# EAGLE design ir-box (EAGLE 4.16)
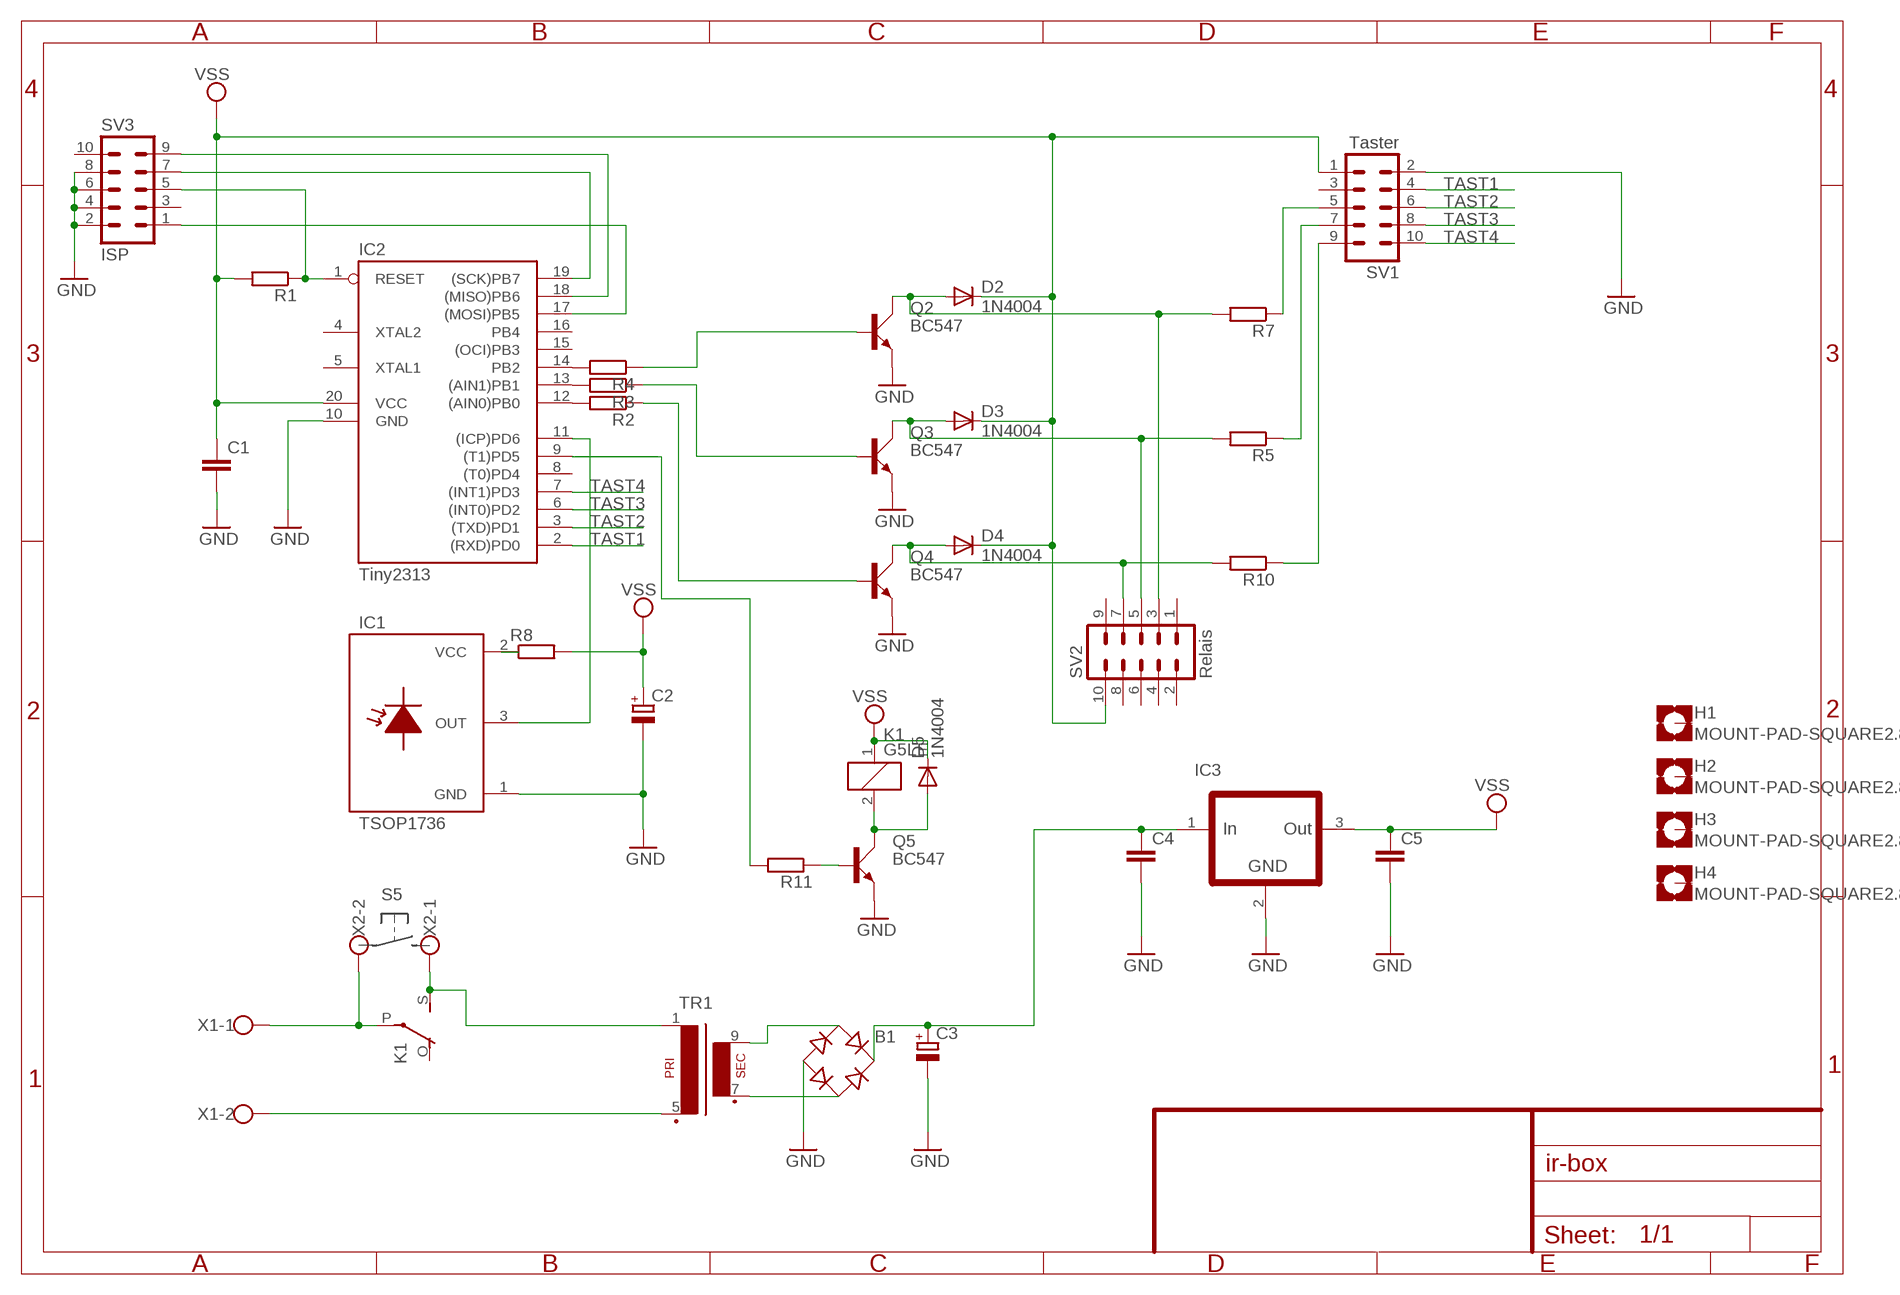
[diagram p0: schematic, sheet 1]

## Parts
B1  B-DIL  [B-DIL]
C1  C-EU050-025X075  [C050-025X075]
C2  CPOL-EUE3.5-8  [E3,5-8]
C3  CPOL-EUE5-13  [E5-13]
C4  C-EU050-025X075  [C050-025X075]
C5  C-EU050-025X075  [C050-025X075]
D2  1N4004  [DO41-10]
D3  1N4004  [DO41-10]
D4  1N4004  [DO41-10]
D5  1N4004  [DO41-10]
H1  MOUNT-PAD-SQUARE2.8  [2,8-PAD-SQUARE]
H2  MOUNT-PAD-SQUARE2.8  [2,8-PAD-SQUARE]
H3  MOUNT-PAD-SQUARE2.8  [2,8-PAD-SQUARE]
H4  MOUNT-PAD-SQUARE2.8  [2,8-PAD-SQUARE]
IC1  TSOP1736  [TSOP]
IC2  Tiny2313  AT90S2313P  [DIL20]
IC3  78XX  [TO220AV]
K1  G5LE  [G5LE]
Q2  BC547  [SOT54A]
Q3  BC547  [SOT54A]
Q4  BC547  [SOT54A]
Q5  BC547  [SOT54A]
R1  R-EU_0204/7  [0204/7]
R2  R-EU_0204/7  [0204/7]
R3  R-EU_0204/7  [0204/7]
R4  R-EU_0204/7  [0204/7]
R5  R-EU_0204/7  [0204/7]
R7  R-EU_0204/7  [0204/7]
R8  R-EU_0204/7  [0204/7]
R10  R-EU_0204/7  [0204/7]
R11  R-EU_0204/7  [0204/7]
SV1  Taster  ML10  [ML10]
SV2  Relais  ML10  [ML10]
SV3  ISP  ML10  [ML10]
TR1  EI42-1  [EI42-1]
X1  W237-2N  [W237-2N]
X2  W237-2N  [W237-2N]

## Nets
GND: B1.- C1.2 C2.- C3.- C4.2 C5.2 IC1.1(GND) IC2.10(GND) IC3.2(GND) Q2.E Q3.E Q4.E Q5.E SV1.2 SV3.2 SV3.4 SV3.6 SV3.8
N$1: IC2.12((AIN0)PB0) R2.2
N$2: IC2.1(RESET) R1.1 SV3.5
N$3: IC2.13((AIN1)PB1) R3.2
N$4: IC2.14(PB2) R4.2
N$7: Q2.B R4.1
N$8: Q3.B R3.1
N$9: Q4.B R2.1
N$11: D2.A Q2.C R7.2 SV2.3
N$12: D3.A Q3.C R5.2 SV2.5
N$13: D4.A Q4.C R10.2 SV2.7
N$14: IC1.3(OUT) IC2.11((ICP)PD6)
N$15: IC1.2(VCC) R8.1
N$16: K1.P(2:P) X1.1 X2.2
N$17: K1.S(2:S) TR1.1 X2.1
N$18: TR1.5 X1.2
N$19: B1.AC2 TR1.7
N$20: B1.AC1 TR1.9
N$21: Q5.B R11.1
N$22: B1.+ C3.+ C4.1 IC3.1(IN)
N$23: D5.A K1.2 Q5.C
N$25: IC2.9((T1)PD5) R11.2
N$27: R7.1 SV1.5
N$28: R5.1 SV1.7
N$29: R10.1 SV1.9
N$30: IC2.17((MOSI)PB5) SV3.1
N$31: IC2.19((SCK)PB7) SV3.7
N$32: IC2.18((MISO)PB6) SV3.9
TAST1: IC2.2((RXD)PD0) SV1.4
TAST2: IC2.3((TXD)PD1) SV1.6
TAST3: IC2.6((INT0)PD2) SV1.8
TAST4: IC2.7((INT1)PD3) SV1.10
VSS: C1.1 C2.+ C5.1 D2.C D3.C D4.C D5.C IC2.20(VCC) IC3.3(OUT) K1.1 R1.2 R8.2 SV1.1 SV2.10
Unconnected: H1.B2,8(MOUNT) H2.B2,8(MOUNT) H3.B2,8(MOUNT) H4.B2,8(MOUNT) IC2.4(XTAL2) IC2.5(XTAL1) IC2.8((T0)PD4) IC2.15((OCI)PB3) IC2.16(PB4) K1.O(2:O) SV1.3 SV2.1 SV2.2 SV2.4 SV2.6 SV2.8 SV2.9 SV3.3 SV3.10

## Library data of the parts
B1 = rectifier:B-DIL: RECTIFIER
C1 C4 C5 = rcl:C-EU: CAPACITOR, European symbol
C2 C3 = rcl:CPOL-EU: POLARIZED CAPACITOR, European symbol
D2-D5 = diode-1:1N4004: DIODE
H1-H4 = holes:MOUNT-PAD-SQUARE: MOUNTING PAD, square
IC1 = andereBauteile:TSOP: TSOP17.. Photo Modules for PCM Remote Control Systems
IC2 = avr:AT90S2313: MICROCONTROLLER 2 Kbytes FLASH 128 bytes SRAM 128 bytes EEPROM UART
IC3 = 0_jmw:78XX
K1 = relay:G5LE: RELAY 1 x switch, 10 A/120 V AC, 8 A/30 V DC, Omron
Q2-Q5 = transistor-small-signal:BC547: NPN TRANSISTOR
R1-R5 R7 R8 R10 R11 = rcl:R-EU_: RESISTOR, European symbol
SV1-SV3 = con-ml:ML10: HARTING
TR1 = trafo:EI42-1: TRANSFORMER 1 primary winding, 1 secondary winding ERA
X1 X2 = con-wago-508:W237-2N: WAGO SREW CLAMP

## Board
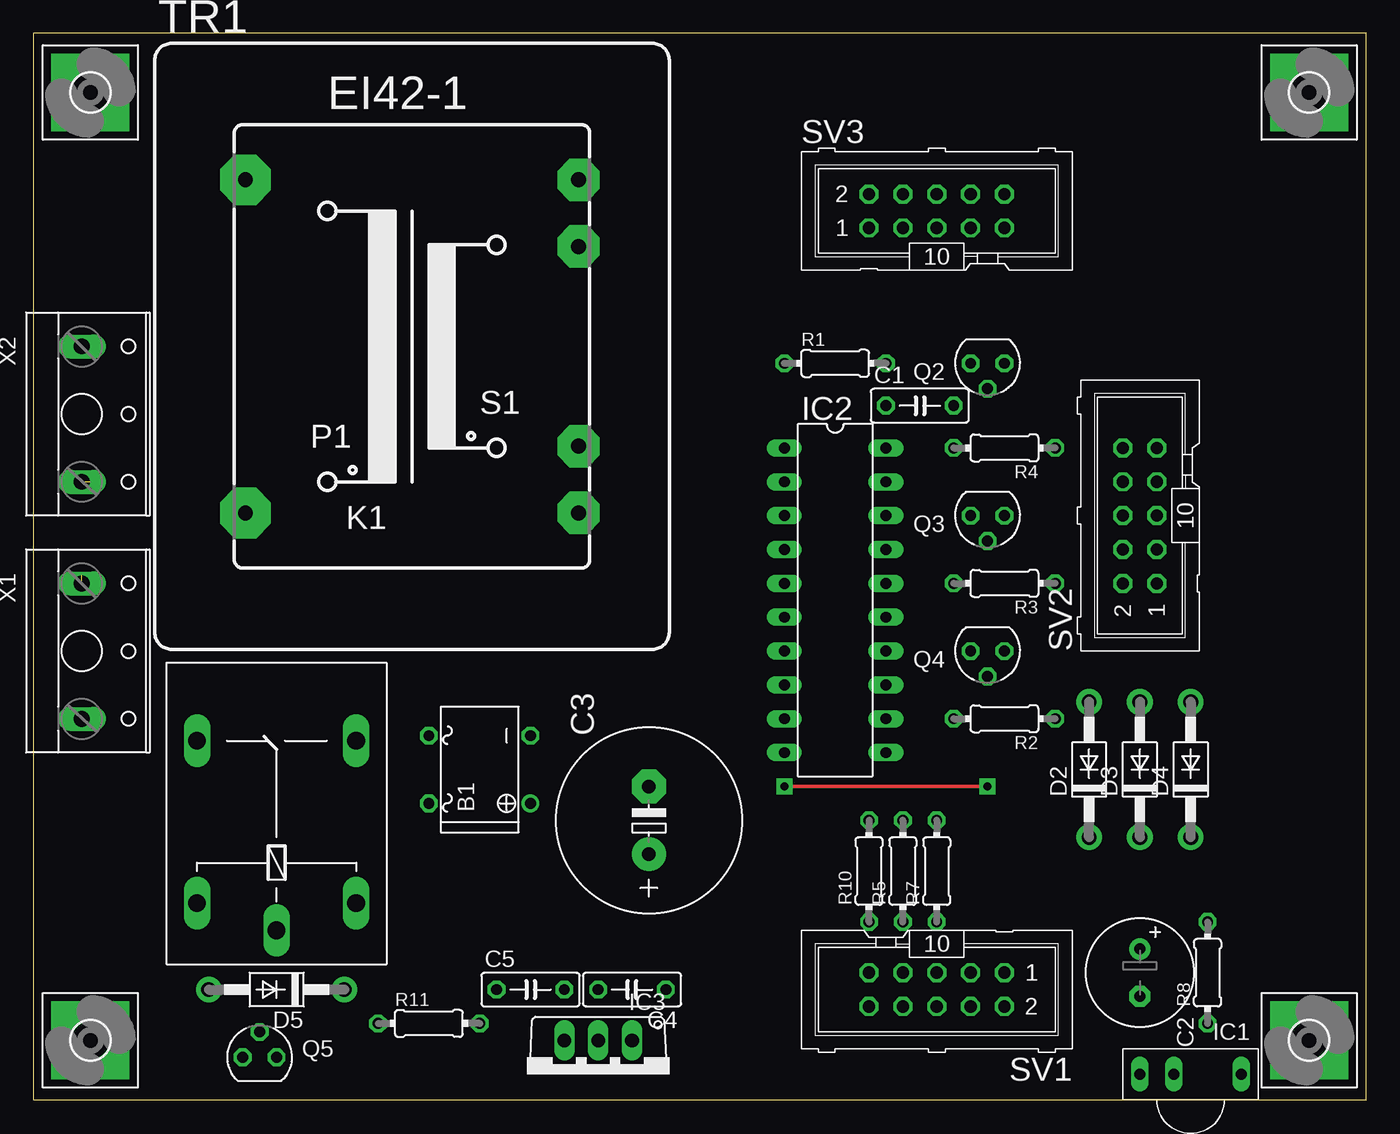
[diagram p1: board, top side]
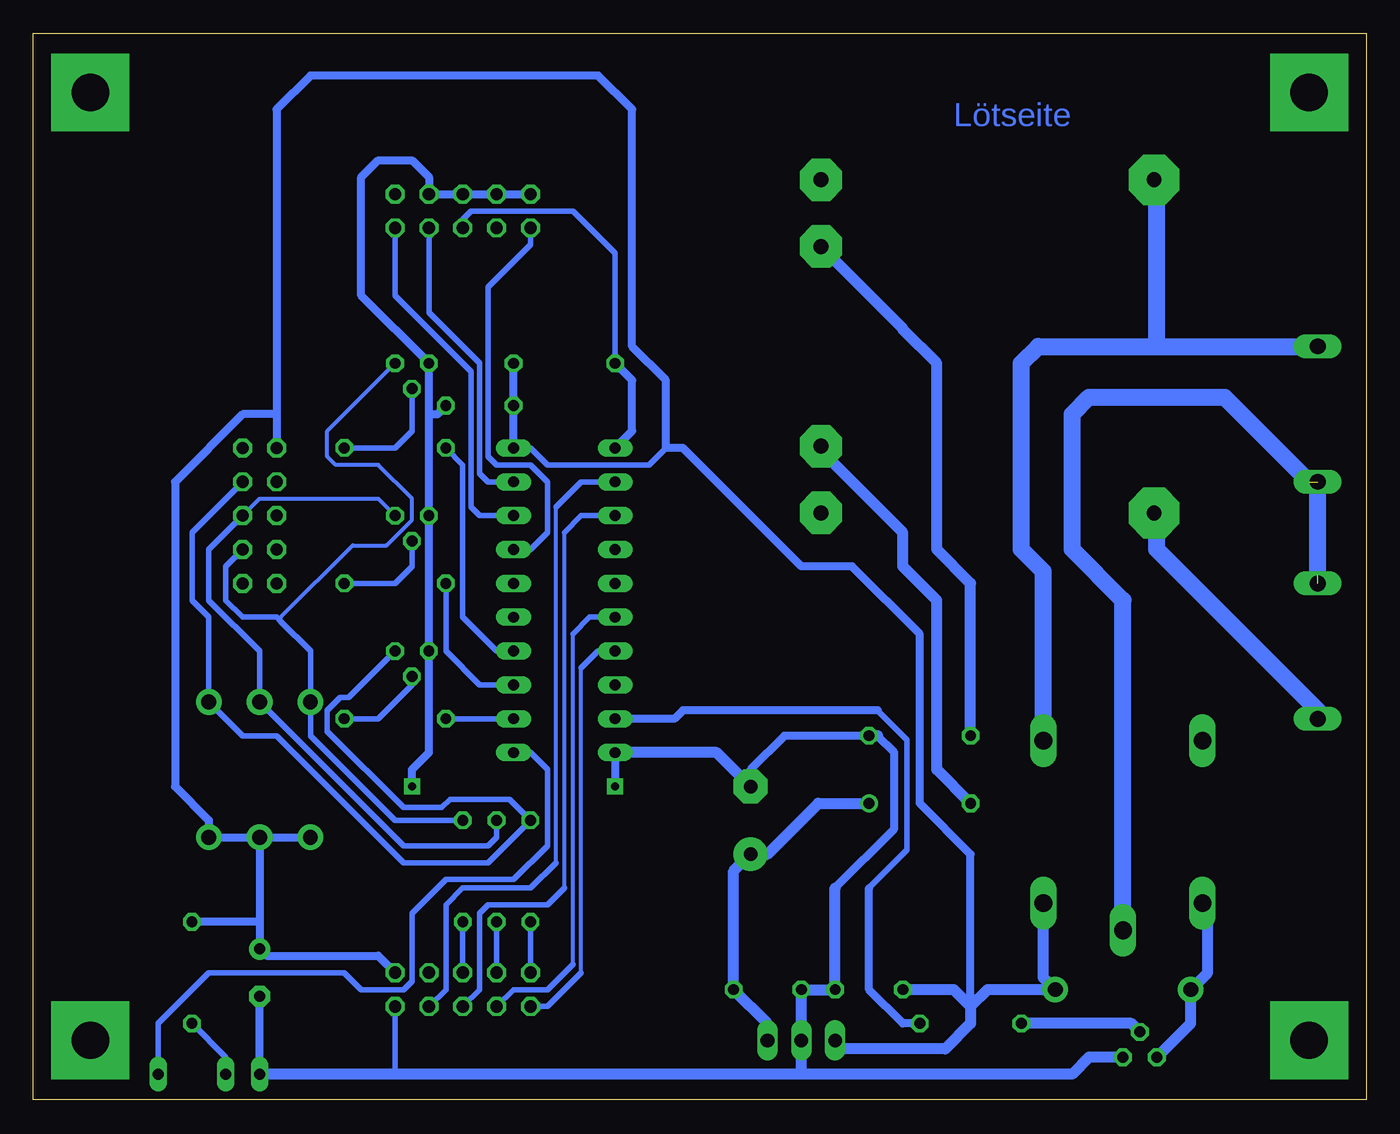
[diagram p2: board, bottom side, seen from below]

Size 100 x 80 mm. Coordinates in mm from the lower left corner, seen from the top.
Outline: 0,0 100,0 100,80 0,80 0,0
Copper layers (1*16): Top 0.035mm / dielectric 1.5mm / Bottom 0.035mm
Design rules "default": minimum track width 10mil, minimum drill 0.4mm, track to track 10mil, track to pad 10mil, pad to pad 10mil, via to via 10mil, smd to smd 10mil, copper to edge 40mil, drill to drill 8mil, minimum pad ring 10mil, minimum via ring 0.3mm, stop-mask expansion 4mil, vias tented up to drill 0mil, thermal gap 10mil

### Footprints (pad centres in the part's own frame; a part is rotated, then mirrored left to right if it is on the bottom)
B-DIL = drill 0.813 round: + -2.54,-3.81 | drill 0.813 octagon: - 2.54,-3.81; AC1 2.54,3.81; AC2 -2.54,3.81
C050-025X075 = drill 0.813 octagon: 1 -2.54,0; 2 2.54,0
E3,5-8 = drill 0.813 pad 1.6 round: + -1.778,0 | drill 0.813 pad 1.6 octagon: - 1.778,0
E5-13 = drill 1.016 pad 2.54 round: + -2.54,0 | drill 1.016 pad 2.54 octagon: - 2.54,0
DO41-10 = drill 1.118 pad 1.93 round: A 5.08,0; C -5.08,0
2,8-PAD-SQUARE = drill 2.8 pad 5.842 square: B2,8 0,0
TSOP = drill 0.813 long: 1 3.81,0; 2 1.27,0; 3 -3.81,0
DIL20 = drill 0.813 long: 1 -11.43,-3.81; 2 -8.89,-3.81; 3 -6.35,-3.81; 4 -3.81,-3.81; 5 -1.27,-3.81; 6 1.27,-3.81; 7 3.81,-3.81; 8 6.35,-3.81; 9 8.89,-3.81; 10 11.43,-3.81; 11 11.43,3.81; 12 8.89,3.81; 13 6.35,3.81; 14 3.81,3.81; 15 1.27,3.81; 16 -1.27,3.81; 17 -3.81,3.81; 18 -6.35,3.81; 19 -8.89,3.81; 20 -11.43,3.81
TO220AV = drill 1.016 long: 1 -2.54,-2.54; 2 0,-2.54; 3 2.54,-2.54
G5LE = drill 1.321 long: 1 -7.493,-5.969; 2 -7.493,5.969; O 4.699,5.969; P -9.525,0; S 4.699,-5.969
SOT54A = drill 0.813 octagon: B 0,1.905; C -1.27,0; E 1.27,0
0204/7 = drill 0.813 octagon: 1 -3.81,0; 2 3.81,0
ML10 = drill 0.914 octagon: 1 -5.08,-1.27; 2 -5.08,1.27; 3 -2.54,-1.27; 4 -2.54,1.27; 5 0,-1.27; 6 0,1.27; 7 2.54,-1.27; 8 2.54,1.27; 9 5.08,-1.27; 10 5.08,1.27
EI42-1 = drill 1.118 pad 3.81 octagon: 1 -12.497,12.497; 5 -12.497,-12.497 | drill 1.118 pad 3.175 octagon: 6 12.497,-12.497; 7 12.497,-7.493; 9 12.497,7.493; 10 12.497,12.497
W237-2N = drill 1.194 long: 1 -5.08,-0.635; 2 5.08,-0.635

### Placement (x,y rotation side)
B1  33.49,24.76 90 top
C1  66.51,52.07 0 top
C2  83.02,9.52 270 top
C3  46.19,20.95 90 top
C4  44.92,8.25 180 top
C5  37.3,8.25 0 top
D2  79.21,24.76 90 top
D3  83.02,24.76 90 top
D4  86.83,24.76 90 top
D5  18.25,8.25 180 top
H1  4.28,4.44 0 top
H2  4.28,75.56 0 top
H3  95.72,75.56 0 top
H4  95.72,4.44 0 top
IC1  86.83,1.9 180 top
IC2  60.16,37.46 270 top
IC3  42.38,1.9 180 top
K1  18.25,22.22 90 top
Q2  71.59,55.24 180 top
Q3  71.59,43.81 180 top
Q4  71.59,33.65 180 top
Q5  16.98,3.17 0 top
R1  60.16,55.24 0 top
R2  72.86,28.57 180 top
R3  72.86,38.73 180 top
R4  72.86,48.89 180 top
R5  65.24,17.14 90 top
R7  67.78,17.14 90 top
R8  88.1,9.52 90 top
R10  62.7,17.14 90 top
R11  29.68,5.71 0 top
SV1  67.78,8.25 180 top
SV2  83.02,43.81 90 top
SV3  67.78,66.67 0 top
TR1  28.41,56.51 0 top
X1  4.28,33.65 270 top
X2  4.28,51.43 270 top

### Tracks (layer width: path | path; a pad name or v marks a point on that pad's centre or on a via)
GND  (via drill 0.6)
  Top 0.254: v56.35,23.49 v71.59,23.49
  Bottom 0.406: 72.86,1.9 SV1.2
  Bottom 0.61: B1.- 43.65,27.3 46.19,24.76 C3.- | 39.84,15.87 35.39,20.31 35.39,26.03 36.66,27.3 | IC1.1 C2.- | SV3.2 SV3.4 SV3.6 SV3.8 70.32,69.21 71.59,70.48 74.13,70.48 75.4,69.21 75.4,60.32 Q2.E 70.32,51.43 | 70.32,51.43 Q3.E Q4.E 70.32,26.03 71.59,24.76 v71.59,23.49 | C1.2 69.69,51.43 70.32,51.43 | IC2.10 v56.35,23.49
  Bottom 0.813: Q5.E 20.79,3.17 22.06,1.9 42.38,1.9 | 42.38,1.9 IC3.2 C4.2 | 42.38,1.9 72.86,1.9 IC1.1 | C4.2 C5.2 | IC2.10 48.73,26.03 C3.- | C4.2 C5.2 | C5.2 39.84,15.87 | 36.66,27.3 B1.-
N$1
  Bottom 0.406: IC2.12 R2.2
N$2
  Bottom 0.406: SV3.5 67.78,66.03 67.14,66.67 59.52,66.67 56.35,63.5 R1.1
  Bottom 0.61: R1.1 55.08,53.97 55.08,50.16 IC2.1
N$3
  Bottom 0.406: R3.2 69.05,33.65 66.51,31.11 IC2.13
N$4
  Bottom 0.406: R4.2 67.78,47.62 67.78,36.19 65.24,33.65 IC2.14
N$7
  Bottom 0.406: Q2.B 71.59,50.16 72.86,48.89 R4.1
N$8
  Bottom 0.406: Q3.B 71.59,40 72.86,38.73 R3.1
N$9
  Bottom 0.406: R2.1 74.13,28.57 71.59,31.11 Q4.B
N$11
  Bottom 0.305: Q2.C 77.94,50.16 77.94,48.26 77.3,47.62 74.13,47.62 71.59,45.08 71.59,43.49 73.5,41.59 76.03,41.59 81.43,36.19 81.43,35.87
  Bottom 0.406: SV2.3 85.56,40 85.56,37.46 84.29,36.19 81.75,36.19 81.43,35.87 79.21,33.65 D2.A 79.21,27.3 72.86,20.95 R7.2
N$12
  Bottom 0.305: SV2.5 83.02,45.08 74.13,45.08 Q3.C
  Bottom 0.406: SV2.5 86.83,41.27 86.83,37.46 83.02,33.65 D3.A 72.22,19.04 65.88,19.04 65.24,19.68 R5.2
N$13
  Bottom 0.406: SV2.7 88.1,42.54 88.1,37.46 86.83,36.19 D4.A 84.29,27.3 81.75,27.3 72.22,17.77 65.88,17.77 R10.2 64.29,22.54 68.73,22.54 69.37,21.9 72.22,21.9 77.94,27.62 77.94,29.2 76.99,30.16 76.35,30.16 Q4.C
N$14
  Bottom 0.406: IC2.11 62.7,26.03 61.43,24.76 61.43,19.04 63.97,16.5 69.05,16.5 71.59,13.97 71.59,8.89 72.22,8.25 75.4,8.25 76.67,9.52 77.3,9.52 86.83,9.52 90.64,5.71 IC1.3
N$15
  Bottom 0.406: IC1.2 85.56,3.17 R8.1
N$16  (2 unrouted)
  Bottom 1.27: X2.2 3.64,39.37 4.28,38.73 | K1.P 18.25,37.46 22.06,41.27 22.06,51.43 20.79,52.7 10.63,52.7 4.28,46.35
N$17
  Bottom 1.27: 15.71,69.01 15.71,69.21 | 15.71,69.01 TR1.1 | 15.71,56.51 X2.1 | 15.71,56.51 15.71,69.01 | K1.S 24.22,39.62 25.87,41.27 25.87,55.24 24.6,56.51 15.71,56.51
N$18
  Bottom 1.27: X1.2 3.64,29.2 15.71,41.27 15.71,43.81 TR1.5
N$19
  Bottom 0.813: TR1.7 41.03,48.89 41.11,48.89 34.76,42.54 34.76,40 32.22,37.46 32.22,24.76 B1.AC2
N$20
  Bottom 0.813: TR1.9 34.76,57.86 34.76,57.78 32.22,55.24 32.22,41.27 29.68,38.73 B1.AC1
N$21
  Bottom 0.813: Q5.B 17.61,5.71 R11.1
N$22
  Bottom 0.813: B1.+ 41.11,22.22 44.92,18.41 C3.+ 47.46,17.14 C4.1 44.92,5.71 IC3.1
N$23
  Bottom 0.813: Q5.C 13.17,5.71 D5.A 11.9,9.52 11.9,14.6 12.03,14.73 K1.2
N$25
  Bottom 0.406: 37.3,15.87 34.44,18.73 34.44,26.98 36.66,29.2
  Bottom 0.61: IC2.9 52.54,28.57 51.91,28.57 51.27,29.2 36.66,29.2 | R11.2 34.76,5.71 37.3,8.25 37.3,15.87
N$27
  Bottom 0.406: SV1.5 R7.1
N$28
  Bottom 0.406: SV1.7 R5.1
N$29
  Bottom 0.406: SV1.9 R10.1
N$30
  Bottom 0.406: SV3.1 62.7,64.13 65.88,60.96 65.88,48.26 65.24,47.62 62.7,47.62 61.43,46.35 61.43,42.54 62.7,41.27 IC2.17
N$31
  Bottom 0.406: IC2.19 65.88,46.35 66.51,46.98 66.51,55.24 70.32,59.05 SV3.7
N$32
  Bottom 0.406: IC2.18 66.51,43.81 67.14,44.45 67.14,54.61 72.86,60.32 SV3.9
TAST1
  Bottom 0.305: 60.8,17.77 60.8,44.45
  Bottom 0.406: SV1.4 69.05,8.25 69.05,14.6 67.78,15.87 62.7,15.87 60.8,17.77 | 60.8,44.45 58.89,46.35 IC2.2
TAST2
  Bottom 0.305: 60.16,15.87 60.16,42.54
  Bottom 0.406: 60.16,15.87 61.43,14.6 65.88,14.6 66.51,13.97 66.51,8.25 SV1.6 | IC2.3 58.89,43.81 60.16,42.54
TAST3
  Bottom 0.305: 59.52,10.16 59.52,34.92
  Bottom 0.406: SV1.8 63.97,8.25 61.43,8.25 59.52,10.16 | IC2.6 58.25,36.19 59.52,34.92
TAST4
  Bottom 0.305: 58.89,9.52 58.89,32.38
  Bottom 0.406: SV1.10 61.43,6.98 58.89,9.52 | 58.89,32.38 57.62,33.65 IC2.7
VSS
  Bottom 0.305: 31.58,3.8 30,5.39 30,5.71 29.68,5.71
  Bottom 0.406: 52.54,48.89 53.81,47.62 61.43,47.62 62.7,48.89 IC2.20
  Bottom 0.61: IC2.20 C1.1 R1.2 | D3.C D2.C | D3.C D4.C 86.83,20.95 89.37,23.49 89.37,46.35 84.29,51.43 81.75,51.43 | 81.75,51.43 81.75,74.29 79.21,76.83 57.62,76.83 55.08,74.29 55.08,56.51 52.54,53.97 52.54,48.89 51.27,48.89 42.38,40 38.57,40 33.49,34.92 33.49,22.22 29.68,18.41 29.68,5.71 | 83.02,13.33 C2.+ 82.51,10.79 74.13,10.79 SV1.1 | D3.C 83.02,13.33 | 83.02,13.33 R8.2 | 81.75,51.43 SV2.10
  Bottom 0.813: K1.1 24.22,9.14 D5.C 28.41,8.25 29.68,6.98 | IC3.3 39.2,3.8 31.58,3.8 29.68,5.71 29.68,6.98 | C5.1 30.95,8.25 29.68,6.98

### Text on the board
Bottom: Lötseite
